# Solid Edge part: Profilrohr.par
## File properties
Username: bmolnar
Dokumentum tartalom típus: 0
Author: bmolnar
Last saved by: bmolnar
Revision: 84
Sűrűség: 0,000 kg/m^3
Pontosság: 0,990
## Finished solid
Body 1: solid body, 91 faces, 266 edges, 176 vertices.
  Faces by surface: plane 46, cylinder 45
  Edges by curve: line 176, circle 90
Bounding box of the edges (mm): 49.000 x 49.000 x 75.800, from (-24.5, -24.5, 0) to (24.5, 24.5, 75.8).
Cylindrical faces by radius (mm): R0.15 x20, R0.25 x20, R8 x4, R16 x1
Planar faces by outward normal: +x 11, +y 11, +z 1, -x 11, -y 11, -z 1
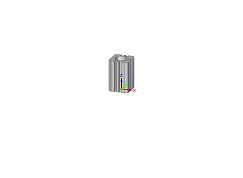
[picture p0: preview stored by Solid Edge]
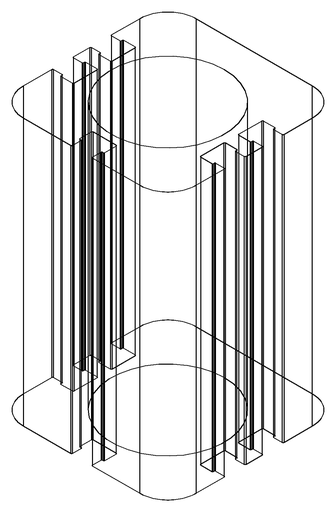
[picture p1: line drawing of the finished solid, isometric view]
